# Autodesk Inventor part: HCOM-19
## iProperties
Author: Mark Case
Shininess: 64.0
Angle Display Precision: 2
Document Length Units: 11272
Document Angle Units: 11286
Document Time Units: 11279
Document Mass Units: 11290
Document Length Units Precision: 3
Document Angle Units Precision: 2
Compacted: True
PropertySet Name: _Private Model Information
Created: 2001-12
Part Number: HCOM-19
Description: 1 3/16" BORE SPHERICAL BEARING
Vendor: Auroa
Document SubType Name: Modeling
Designer: Charles Bliss
Control State: 0
Master: False
Checked Out: False
PropertySet Name: Design Tracking Control
Density: 0.0
Volumn: 0.0
Area: 0.0
PropertySet Name: Model Information
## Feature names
1. Revolution1
2. Revolution2
3. Revolution3
